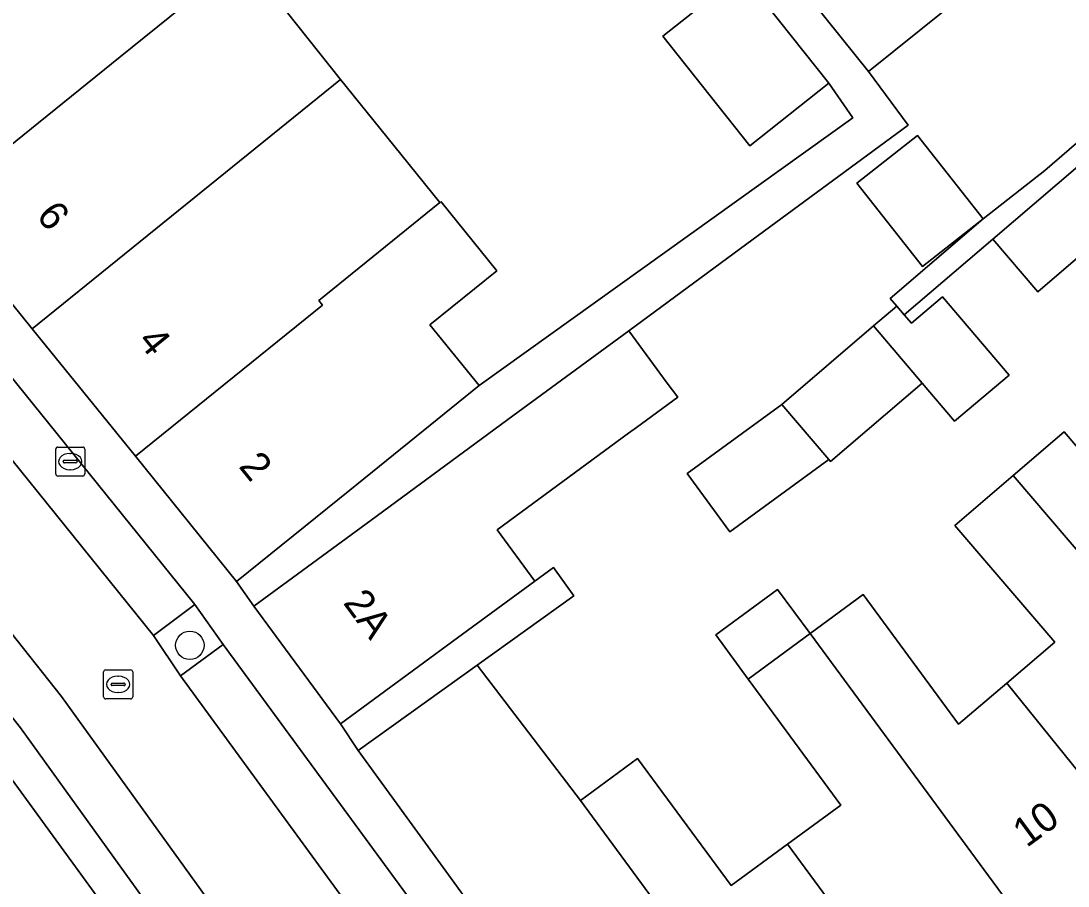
# Model space of a CAD drawing. Extents: x 161881 to 162523, y 381678 to 382381.
# Drawn here: x 162256.2 to 162292.22, y 381951.01 to 381980.78 of the extents above; entities that cross this region are included whole.
import ezdxf

# ---------------------------------------------------------------- set-up
doc = ezdxf.new("R2010")
doc.units = 0
for name, color, linetype in [('IMGEO_Boom', 7, 'Continuous'), ('IMGEO_Brandkraan', 7, 'Continuous'), ('IMGEO_Erf', 7, 'Continuous'), ('IMGEO_Groenvoorziening', 7, 'Continuous'), ('IMGEO_Kolk', 7, 'Continuous'), ('IMGEO_Pand', 7, 'Continuous'), ('IMGEO_Pand_nummerreeks', 7, 'Continuous'), ('IMGEO_Parkeervlak_open', 7, 'Continuous'), ('IMGEO_Rijbaan_lokaal_open', 7, 'Continuous'), ('IMGEO_Voetpad_open', 7, 'Continuous')]:
    doc.layers.add(name, color=color, linetype=linetype)

msp = doc.modelspace()

# ---------------------------------------------------------------- linework, layer by layer
at = {"layer": 'IMGEO_Boom'}
msp.add_circle((162262.01, 381959.292), 0.489, dxfattribs=at)
at = {"layer": 'IMGEO_Brandkraan'}
for p, q in [((162257.396, 381965.189), (162257.396, 381966.041)), ((162257.471, 381966.115), (162258.323, 381966.115)), ((162257.884, 381965.895), (162257.909, 381965.895)), ((162258.397, 381966.041), (162258.397, 381965.189)), ((162257.655, 381965.609), (162257.655, 381965.621)), ((162258.093, 381965.572), (162257.695, 381965.572)), ((162257.698, 381965.658), (162258.096, 381965.658)), ((162258.139, 381965.621), (162258.139, 381965.609)), ((162258.323, 381965.115), (162257.471, 381965.115)), ((162257.907, 381965.335), (162257.882, 381965.335))]:
    msp.add_line(p, q, dxfattribs=at)
for points in [[(162257.396, 381965.189), (162257.396, 381966.041)], [(162257.471, 381966.115), (162258.323, 381966.115)], [(162258.397, 381966.041), (162258.397, 381965.189)], [(162258.323, 381965.115), (162257.471, 381965.115)]]:
    msp.add_lwpolyline(points, dxfattribs=at)
for centre, radius, start, end in [((162257.473, 381966.039), 0.0765, 91.552, 178.448), ((162257.473, 381966.039), 0.0765, 91.552, 178.448), ((162258.321, 381966.039), 0.0765, 1.552, 88.448), ((162258.321, 381966.039), 0.0765, 1.552, 88.448), ((162257.695, 381965.618), 0.0403, 85.8775, 175.7526), ((162257.692, 381965.608), 0.0366, 178.938, 274.7102), ((162258.096, 381965.615), 0.043, 264.8664, 352.4533), ((162258.1, 381965.62), 0.0386, 1.7309, 96.639), ((162257.473, 381965.191), 0.0765, 181.552, 268.448), ((162257.473, 381965.191), 0.0765, 181.552, 268.448), ((162258.321, 381965.191), 0.0765, 271.552, 358.448), ((162258.321, 381965.191), 0.0765, 271.552, 358.448)]:
    msp.add_arc(centre, radius, start, end, dxfattribs=at)
for centre, major_axis, ratio, start_param, end_param in [((162257.883, 381965.615), (-0.387, 0.002), 0.722429, 4.712389, 7.853982), ((162257.908, 381965.615), (-0.39, 0.002), 0.717154, 1.570796, 4.712389)]:
    msp.add_ellipse(centre, major_axis=major_axis, ratio=ratio, start_param=start_param, end_param=end_param, dxfattribs=at)
at = {"layer": 'IMGEO_Erf'}
for points in [[(162263.853, 381982.975), (162267.194, 381978.758), (162269.022, 381976.495), (162270.613, 381974.526), (162270.65, 381974.556), (162272.57, 381972.179), (162270.27, 381970.32), (162271.962, 381968.227), (162284.816, 381977.446), (162283.991, 381978.635), (162281.269, 381976.477), (162278.277, 381980.251), (162280.998, 381982.409)], [(162288.836, 381981.842), (162285.355, 381979.041), (162286.719, 381977.186), (162281.165, 381973.101), (162277.105, 381970.115), (162278.433, 381968.312), (162278.79, 381967.827), (162277.375, 381966.786), (162277.103, 381966.586), (162272.583, 381963.262), (162273.876, 381961.504), (162274.515, 381961.973), (162275.217, 381960.997), (162271.892, 381958.607), (162275.442, 381953.947), (162277.413, 381955.397), (162280.63, 381951.023), (162282.568, 381952.448), (162284.403, 381953.797), (162281.218, 381958.127), (162280.099, 381959.648), (162282.229, 381961.215), (162283.348, 381959.694), (162285.173, 381961.036), (162288.454, 381956.575), (162290.112, 381957.991), (162291.763, 381959.402), (162288.329, 381963.42), (162290.331, 381965.132), (162292.088, 381966.633), (162295.619, 381962.502)], [(162294.812, 381974.571), (162291.175, 381971.46), (162289.627, 381973.269), (162286.582, 381970.665), (162286.829, 381970.374), (162287.902, 381971.285), (162290.189, 381968.589), (162288.315, 381967), (162287.201, 381968.312), (162284.048, 381965.615), (162283.988, 381965.685), (162280.585, 381963.199), (162279.119, 381965.205), (162282.368, 381967.579), (162285.529, 381970.283), (162286.327, 381970.966), (162286.103, 381971.231), (162289.3, 381973.964), (162291.417, 381975.628), (162296.949, 381980.401)]]:
    msp.add_lwpolyline(points, dxfattribs=at)
msp.add_lwpolyline([(162289.3, 381973.964), (162287.213, 381972.323), (162284.954, 381975.197), (162287.042, 381976.837)], close=True, dxfattribs=at)
at = {"layer": 'IMGEO_Groenvoorziening'}
msp.add_lwpolyline([(162261.693, 381958.246), (162263.159, 381959.315), (162262.184, 381960.692), (162260.754, 381959.631)], close=True, dxfattribs=at)
at = {"layer": 'IMGEO_Kolk'}
for p, q in [((162259.044, 381957.522), (162259.044, 381958.374)), ((162259.119, 381958.448), (162259.971, 381958.448)), ((162260.045, 381958.374), (162260.045, 381957.522)), ((162259.303, 381957.942), (162259.303, 381957.954)), ((162259.741, 381957.905), (162259.343, 381957.905)), ((162259.346, 381957.991), (162259.744, 381957.991)), ((162259.532, 381958.228), (162259.557, 381958.228)), ((162259.787, 381957.954), (162259.787, 381957.942)), ((162259.555, 381957.668), (162259.53, 381957.668)), ((162259.971, 381957.448), (162259.119, 381957.448))]:
    msp.add_line(p, q, dxfattribs=at)
for points in [[(162259.044, 381957.522), (162259.044, 381958.374)], [(162259.119, 381958.448), (162259.971, 381958.448)], [(162260.045, 381958.374), (162260.045, 381957.522)], [(162259.971, 381957.448), (162259.119, 381957.448)]]:
    msp.add_lwpolyline(points, dxfattribs=at)
for centre, radius, start, end in [((162259.121, 381958.372), 0.0765, 91.552, 178.448), ((162259.121, 381958.372), 0.0765, 91.552, 178.448), ((162259.969, 381958.372), 0.0765, 1.552, 88.448), ((162259.969, 381958.372), 0.0765, 1.552, 88.448), ((162259.343, 381957.951), 0.0403, 85.8775, 175.7526), ((162259.34, 381957.941), 0.0366, 178.938, 274.7102), ((162259.744, 381957.948), 0.043, 264.8664, 352.4533), ((162259.748, 381957.953), 0.0386, 1.7309, 96.639), ((162259.121, 381957.524), 0.0765, 181.552, 268.448), ((162259.121, 381957.524), 0.0765, 181.552, 268.448), ((162259.969, 381957.524), 0.0765, 271.552, 358.448), ((162259.969, 381957.524), 0.0765, 271.552, 358.448)]:
    msp.add_arc(centre, radius, start, end, dxfattribs=at)
for centre, major_axis, ratio, start_param, end_param in [((162259.531, 381957.948), (-0.387, 0.002), 0.722429, 4.712389, 7.853982), ((162259.556, 381957.948), (-0.39, 0.002), 0.717154, 1.570796, 4.712389)]:
    msp.add_ellipse(centre, major_axis=major_axis, ratio=ratio, start_param=start_param, end_param=end_param, dxfattribs=at)
at = {"layer": 'IMGEO_Pand'}
for points in [[(162263.853, 381982.975), (162263.191, 381983.795), (162262.158, 381985.072), (162260.442, 381987.195), (162249.797, 381978.591), (162253.208, 381974.369), (162259.611, 381979.545)], [(162288.836, 381981.842), (162286.546, 381984.689), (162284.205, 381982.806), (162283.064, 381981.889), (162283.431, 381981.433), (162285.355, 381979.041)], [(162267.194, 381978.758), (162263.853, 381982.975), (162259.611, 381979.545), (162253.208, 381974.369), (162256.588, 381970.186)], [(162280.998, 381982.409), (162278.277, 381980.251), (162281.269, 381976.477), (162283.991, 381978.635)], [(162270.613, 381974.526), (162269.022, 381976.495), (162267.194, 381978.758), (162256.588, 381970.186), (162260.135, 381965.797), (162266.571, 381970.998), (162266.443, 381971.157)], [(162287.042, 381976.837), (162284.954, 381975.197), (162287.213, 381972.323), (162289.3, 381973.964)], [(162294.812, 381974.571), (162293.506, 381976.098), (162293.265, 381976.38), (162289.627, 381973.269), (162291.175, 381971.46)], [(162271.962, 381968.227), (162270.27, 381970.32), (162272.57, 381972.179), (162270.65, 381974.556), (162270.613, 381974.526), (162266.443, 381971.157), (162266.571, 381970.998), (162260.135, 381965.797), (162263.619, 381961.485), (162267.509, 381964.628), (162270.032, 381966.667)], [(162286.582, 381970.665), (162286.327, 381970.966), (162285.529, 381970.283), (162287.201, 381968.312), (162288.315, 381967), (162290.189, 381968.589), (162287.902, 381971.285), (162286.829, 381970.374)], [(162287.201, 381968.312), (162285.529, 381970.283), (162282.368, 381967.579), (162283.988, 381965.685), (162284.048, 381965.615)], [(162277.105, 381970.115), (162273.118, 381967.183), (162268.244, 381963.598), (162264.216, 381960.635), (162267.193, 381956.588), (162271.221, 381959.551), (162273.876, 381961.504), (162272.583, 381963.262), (162277.103, 381966.586), (162277.375, 381966.786), (162278.79, 381967.827), (162278.433, 381968.312)], [(162283.988, 381965.685), (162282.368, 381967.579), (162279.119, 381965.205), (162280.585, 381963.199)], [(162298.647, 381955.409), (162302.261, 381958.498), (162297.478, 381964.09), (162295.619, 381962.502), (162292.088, 381966.633), (162290.331, 381965.132)], [(162294.831, 381952.149), (162298.647, 381955.409), (162290.331, 381965.132), (162288.329, 381963.42), (162291.763, 381959.402), (162290.112, 381957.991)], [(162283.348, 381959.694), (162282.229, 381961.215), (162280.099, 381959.648), (162281.218, 381958.127)], [(162294.831, 381952.149), (162290.112, 381957.991), (162288.454, 381956.575), (162285.173, 381961.036), (162283.348, 381959.694), (162290.982, 381949.318)], [(162283.348, 381959.694), (162281.218, 381958.127), (162284.403, 381953.797), (162282.568, 381952.448), (162287.017, 381946.401), (162290.982, 381949.318)], [(162275.442, 381953.947), (162271.892, 381958.607), (162267.802, 381955.667), (162278.431, 381941.04), (162279.505, 381940.876), (162283.109, 381943.527)], [(162258.907, 381950.535), (162255.061, 381955.795), (162245.352, 381948.172), (162245.562, 381947.882), (162248.956, 381943.21), (162252.408, 381945.751), (162254.881, 381947.571)], [(162282.568, 381952.448), (162280.63, 381951.023), (162277.413, 381955.397), (162275.442, 381953.947), (162283.109, 381943.527), (162287.017, 381946.401)]]:
    msp.add_lwpolyline(points, close=True, dxfattribs=at)
at = {"layer": 'IMGEO_Parkeervlak_open'}
for points in [[(162247.432, 381978.966), (162246.074, 381977.838), (162260.754, 381959.631), (162262.184, 381960.692)], [(162243.291, 381975.571), (162241.902, 381974.46), (162249.437, 381964.96), (162256.181, 381956.455), (162264.255, 381945.235), (162269.9, 381937.391), (162271.344, 381938.429), (162265.697, 381946.277), (162257.599, 381957.53), (162250.83, 381966.065)], [(162263.159, 381959.315), (162261.693, 381958.246), (162269.077, 381948.12), (162274.491, 381940.695), (162275.957, 381941.764), (162272.74, 381946.245)]]:
    msp.add_lwpolyline(points, close=True, dxfattribs=at)
at = {"layer": 'IMGEO_Rijbaan_lokaal_open'}
for points in [[(162260.754, 381959.631), (162246.074, 381977.838), (162244.861, 381979.365), (162246.175, 381980.481), (162247.432, 381978.966), (162262.184, 381960.692), (162263.159, 381959.315), (162272.74, 381946.245), (162275.957, 381941.764), (162274.491, 381940.695), (162269.077, 381948.12), (162261.693, 381958.246)], [(162242.214, 381976.929), (162243.291, 381975.571), (162250.83, 381966.065), (162257.599, 381957.53), (162265.697, 381946.277), (162271.344, 381938.429), (162269.9, 381937.391), (162264.255, 381945.235), (162256.181, 381956.455), (162249.437, 381964.96), (162241.902, 381974.46), (162240.825, 381975.85)]]:
    msp.add_lwpolyline(points, close=True, dxfattribs=at)
msp.add_lwpolyline([(162255.061, 381955.795), (162258.907, 381950.535), (162259.49, 381949.726), (162262.789, 381945.152), (162265.743, 381941.056), (162270.07, 381935.019), (162269.88, 381933.866), (162279.505, 381940.876), (162278.431, 381941.04), (162267.802, 381955.667), (162267.193, 381956.588), (162264.216, 381960.635), (162263.619, 381961.485), (162260.135, 381965.797), (162256.588, 381970.186), (162253.208, 381974.369)], dxfattribs=at)
at = {"layer": 'IMGEO_Voetpad_open'}
msp.add_lwpolyline([(162280.998, 381982.409), (162283.991, 381978.635), (162284.816, 381977.446), (162271.962, 381968.227), (162270.032, 381966.667), (162267.509, 381964.628), (162263.619, 381961.485), (162264.216, 381960.635), (162268.244, 381963.598), (162273.118, 381967.183), (162277.105, 381970.115), (162281.165, 381973.101), (162286.719, 381977.186), (162285.355, 381979.041), (162283.431, 381981.433)], dxfattribs=at)
for points in [[(162303.518, 381973.503), (162297.298, 381980.704), (162296.949, 381980.401), (162291.417, 381975.628), (162289.3, 381973.964), (162286.103, 381971.231), (162286.327, 381970.966), (162286.582, 381970.665), (162289.627, 381973.269), (162293.265, 381976.38), (162293.506, 381976.098), (162297.224, 381979.274), (162304.897, 381970.29), (162306.36, 381968.577), (162309.608, 381964.776), (162310.436, 381965.492)], [(162273.876, 381961.504), (162271.221, 381959.551), (162267.193, 381956.588), (162267.802, 381955.667), (162271.892, 381958.607), (162275.217, 381960.997), (162274.515, 381961.973)]]:
    msp.add_lwpolyline(points, close=True, dxfattribs=at)

# ---------------------------------------------------------------- texts
at = {"layer": 'IMGEO_Pand_nummerreeks'}
for s, rotation, p in [('6', 308.938, (162256.698, 381974.061)), ('4', 308.938, (162260.182, 381969.75)), ('2', 308.938, (162263.664, 381965.44)), ('2A', 306.3368, (162267.258, 381960.752)), ('10', 36.3419, (162290.794, 381952.309))]:
    msp.add_text(s, height=1, rotation=rotation, dxfattribs=at).set_placement(p)

doc.saveas('drawing.dxf')
